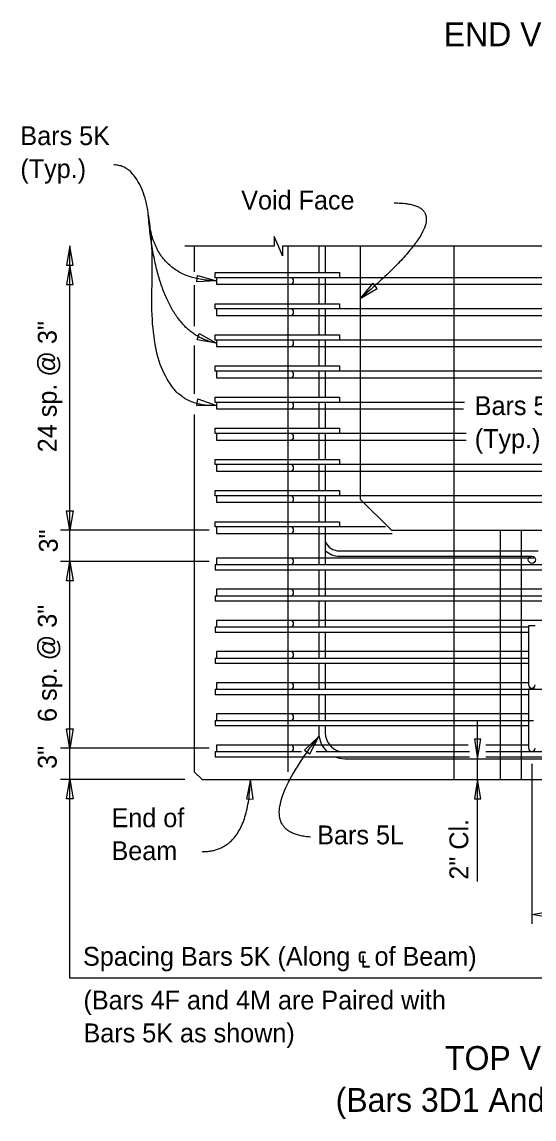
# Model space of a CAD drawing. Extents: x 120658.6 to 120712.1, y 120647.1 to 120669.9.
# Drawn here: x 120659.29 to 120663.4, y 120649.38 to 120658.18 of the extents above; entities that cross this region are included whole.
import ezdxf

# ---------------------------------------------------------------- set-up
doc = ezdxf.new("R2010")
doc.units = 0
for name, color, linetype in [('BeamConc', 7, 'Continuous'), ('BeamConc_h', 7, 'Continuous'), ('Dimension', 7, 'Continuous'), ('Miscellaneous', 7, 'Continuous'), ('Rebar', 7, 'Continuous'), ('Rebar_h', 7, 'Continuous'), ('TextStructures', 7, 'Continuous')]:
    doc.layers.add(name, color=color, linetype=linetype)

msp = doc.modelspace()

# ---------------------------------------------------------------- linework, layer by layer
at = {"layer": 'BeamConc'}
for p, q in [((120660.675, 120656.3833), (120660.675, 120656.1777)), ((120662.0083, 120656.3833), (120662.0083, 120654.3531)), ((120660.675, 120656.0699), (120660.675, 120655.7418)), ((120660.675, 120655.5846), (120660.675, 120655.1981)), ((120660.675, 120655.0319), (120660.675, 120652.1656)), ((120662.0083, 120654.3531), (120662.2583, 120654.1031)), ((120662.2583, 120654.1031), (120666.4578, 120654.1031)), ((120660.675, 120652.1656), (120660.7375, 120652.1031)), ((120660.7375, 120652.1031), (120668.4636, 120652.1031))]:
    msp.add_line(p, q, dxfattribs=at)
at = {"layer": 'BeamConc_h'}
for p, q in [((120661.425, 120656.3833), (120661.425, 120652.1656)), ((120662.7583, 120656.3833), (120662.7583, 120652.1031))]:
    msp.add_line(p, q, dxfattribs=at)
at = {"layer": 'Dimension'}
for p, q in [((120659.6749, 120650.5097), (120659.6749, 120656.3864)), ((120660.7937, 120654.1031), (120659.5993, 120654.1031)), ((120660.7937, 120653.8531), (120659.5993, 120653.8531)), ((120662.9508, 120651.2852), (120662.9508, 120652.5723)), ((120660.7937, 120652.3531), (120659.5993, 120652.3531)), ((120662.4652, 120652.2698), (120662.4652, 120652.2698)), ((120663.3862, 120652.2276), (120663.3862, 120650.9437)), ((120660.5993, 120652.1031), (120659.5993, 120652.1031)), ((120662.4652, 120652.1031), (120662.4652, 120652.1031)), ((120664.0762, 120650.5097), (120659.6749, 120650.5097))]:
    msp.add_line(p, q, dxfattribs=at)
for points in [[(120662.0839, 120656.3833), (120661.3846, 120656.3833), (120661.3846, 120656.3058), (120661.3509, 120656.3833), (120661.3171, 120656.4608), (120661.3171, 120656.3833), (120660.5994, 120656.3833)], [(120668.0994, 120656.3833), (120665.1358, 120656.3833), (120665.1358, 120656.3058), (120665.102, 120656.3833), (120665.0683, 120656.4608), (120665.0683, 120656.3833), (120662.0839, 120656.3833)]]:
    msp.add_lwpolyline(points, dxfattribs=at)
for points in [[(120659.6749, 120656.3864), (120659.6484, 120656.2302), (120659.7014, 120656.2302)], [(120659.6749, 120656.2302), (120659.6484, 120656.0741), (120659.7014, 120656.0741)], [(120660.8531, 120656.1041), (120660.6949, 120656.0954), (120660.7009, 120656.148)], [(120662.0083, 120655.9628), (120662.1444, 120656.0439), (120662.1101, 120656.0842)], [(120660.8531, 120655.604), (120660.6972, 120655.6318), (120660.715, 120655.6817)], [(120660.8531, 120655.104), (120660.6947, 120655.1046), (120660.7037, 120655.1567)], [(120659.6749, 120654.1031), (120659.6485, 120654.2593), (120659.7014, 120654.2593)], [(120659.6749, 120653.8529), (120659.7016, 120653.6972), (120659.6483, 120653.6972)], [(120659.6749, 120652.3529), (120659.6482, 120652.5085), (120659.7016, 120652.5085)], [(120661.675, 120652.4493), (120661.561, 120652.3393), (120661.6036, 120652.3079)], [(120662.9507, 120652.2697), (120662.9774, 120652.4254), (120662.9241, 120652.4254)], [(120659.6749, 120652.1031), (120659.7014, 120651.9469), (120659.6485, 120651.9469)], [(120661.1256, 120652.1031), (120661.0943, 120651.9478), (120661.1472, 120651.9462)], [(120662.9507, 120652.1031), (120662.9241, 120651.9474), (120662.9774, 120651.9474)], [(120663.3862, 120651.0193), (120663.5419, 120651.0459), (120663.5419, 120650.9926)]]:
    msp.add_lwpolyline(points, close=True, dxfattribs=at)
for points in [[(120660.8529, 120655.1038), (120660.3053, 120655.0737), (120660.3647, 120657.0255), (120660.0298, 120657.035)], [(120662.2805, 120656.7296), (120662.9086, 120656.7296), (120662.0083, 120655.9628)], [(120660.8529, 120655.6038), (120660.3843, 120655.6901), (120660.3053, 120656.6311)], [(120660.8529, 120656.1038), (120660.3497, 120656.1141), (120660.3053, 120656.6311)], [(120661.6081, 120651.641), (120661.0763, 120651.677), (120661.675, 120652.4493)], [(120660.7386, 120651.5238), (120661.1076, 120651.5238), (120661.1256, 120652.1031)]]:
    msp.add_open_spline(points, degree=2, dxfattribs=at)
at = {"layer": 'Miscellaneous'}
for p, q in [((120663.1328, 120654.1031), (120663.1328, 120652.1031)), ((120663.2995, 120654.1031), (120663.2995, 120652.1031))]:
    msp.add_line(p, q, dxfattribs=at)
at = {"layer": 'Rebar'}
for p, q in [((120661.675, 120656.3833), (120661.675, 120656.1709)), ((120661.7271, 120656.3833), (120661.7271, 120656.1709)), ((120660.8416, 120656.1709), (120661.8417, 120656.1709)), ((120660.8416, 120656.1292), (120660.8416, 120656.1709)), ((120661.8417, 120656.1292), (120660.8416, 120656.1292)), ((120661.447, 120656.1292), (120660.8531, 120656.1292)), ((120660.8531, 120656.1292), (120660.8531, 120656.0771)), ((120661.675, 120656.1292), (120661.675, 120655.9209)), ((120661.7271, 120656.1292), (120661.7271, 120655.9209)), ((120661.8417, 120656.1709), (120661.8417, 120656.1292)), ((120660.8531, 120656.0771), (120661.447, 120656.0771)), ((120660.8416, 120655.9209), (120661.8417, 120655.9209)), ((120660.8416, 120655.8792), (120660.8416, 120655.9209)), ((120661.8417, 120655.9209), (120661.8417, 120655.8792)), ((120661.8417, 120655.8792), (120660.8416, 120655.8792)), ((120661.447, 120655.8792), (120660.8531, 120655.8792)), ((120660.8531, 120655.8792), (120660.8531, 120655.8271)), ((120661.675, 120655.8792), (120661.675, 120655.6709)), ((120661.7271, 120655.8792), (120661.7271, 120655.6709)), ((120660.8531, 120655.8271), (120661.447, 120655.8271)), ((120660.8416, 120655.6709), (120661.8417, 120655.6709)), ((120660.8416, 120655.6292), (120660.8416, 120655.6709)), ((120661.8417, 120655.6709), (120661.8417, 120655.6292)), ((120661.8417, 120655.6292), (120660.8416, 120655.6292)), ((120661.447, 120655.6292), (120660.8531, 120655.6292)), ((120660.8531, 120655.6292), (120660.8531, 120655.5771)), ((120660.8531, 120655.5771), (120661.447, 120655.5771)), ((120661.675, 120655.6292), (120661.675, 120655.4209)), ((120661.7271, 120655.6292), (120661.7271, 120655.4209)), ((120660.8416, 120655.4209), (120661.8417, 120655.4209)), ((120660.8416, 120655.3792), (120660.8416, 120655.4209)), ((120661.8417, 120655.4209), (120661.8417, 120655.3792)), ((120661.8417, 120655.3792), (120660.8416, 120655.3792)), ((120661.447, 120655.3792), (120660.8531, 120655.3792)), ((120660.8531, 120655.3792), (120660.8531, 120655.3271)), ((120660.8531, 120655.3271), (120661.447, 120655.3271)), ((120661.675, 120655.3792), (120661.675, 120655.1709)), ((120661.7271, 120655.3792), (120661.7271, 120655.1709)), ((120660.8416, 120655.1709), (120661.8417, 120655.1709)), ((120660.8416, 120655.1292), (120660.8416, 120655.1709)), ((120661.8417, 120655.1292), (120660.8416, 120655.1292)), ((120661.447, 120655.1292), (120660.8531, 120655.1292)), ((120660.8531, 120655.1292), (120660.8531, 120655.0771)), ((120661.675, 120655.1292), (120661.675, 120654.9209)), ((120661.7271, 120655.1292), (120661.7271, 120654.9209)), ((120661.8417, 120655.1709), (120661.8417, 120655.1292)), ((120660.8531, 120655.0771), (120661.447, 120655.0771)), ((120660.8416, 120654.9209), (120661.8417, 120654.9209)), ((120660.8416, 120654.8792), (120660.8416, 120654.9209)), ((120661.8417, 120654.8792), (120660.8416, 120654.8792)), ((120661.447, 120654.8792), (120660.8531, 120654.8792)), ((120660.8531, 120654.8792), (120660.8531, 120654.8271)), ((120661.675, 120654.8792), (120661.675, 120654.6709)), ((120661.7271, 120654.8792), (120661.7271, 120654.6709)), ((120661.8417, 120654.9209), (120661.8417, 120654.8792)), ((120660.8531, 120654.8271), (120661.447, 120654.8271)), ((120660.8416, 120654.6709), (120661.8417, 120654.6709)), ((120660.8416, 120654.6292), (120660.8416, 120654.6709)), ((120661.8417, 120654.6292), (120660.8416, 120654.6292)), ((120661.447, 120654.6292), (120660.8531, 120654.6292)), ((120660.8531, 120654.6292), (120660.8531, 120654.5771)), ((120661.675, 120654.6292), (120661.675, 120654.4209)), ((120661.7271, 120654.6292), (120661.7271, 120654.4209)), ((120661.8417, 120654.6709), (120661.8417, 120654.6292)), ((120660.8531, 120654.5771), (120661.447, 120654.5771)), ((120660.8416, 120654.4209), (120661.8417, 120654.4209)), ((120660.8416, 120654.3792), (120660.8416, 120654.4209)), ((120661.8417, 120654.3792), (120660.8416, 120654.3792)), ((120661.447, 120654.3792), (120660.8531, 120654.3792)), ((120660.8531, 120654.3792), (120660.8531, 120654.3271)), ((120661.675, 120654.3792), (120661.675, 120654.1709)), ((120661.7271, 120654.3792), (120661.7271, 120654.1709)), ((120661.8417, 120654.4209), (120661.8417, 120654.3792)), ((120660.8531, 120654.3271), (120661.447, 120654.3271)), ((120660.8416, 120654.1709), (120661.8417, 120654.1709)), ((120660.8416, 120654.1292), (120660.8416, 120654.1709)), ((120661.8417, 120654.1709), (120661.8417, 120654.1292)), ((120661.8417, 120654.1292), (120660.8416, 120654.1292)), ((120661.447, 120654.1292), (120660.8531, 120654.1292)), ((120660.8531, 120654.1292), (120660.8531, 120654.0771)), ((120660.8531, 120654.0771), (120661.447, 120654.0771)), ((120661.675, 120654.1292), (120661.675, 120653.8271)), ((120661.7271, 120654.1292), (120661.7271, 120653.8271)), ((120661.8414, 120653.8948), (120663.386, 120653.8948)), ((120661.8417, 120653.9365), (120663.4354, 120653.9365)), ((120660.8417, 120653.8271), (120660.8417, 120653.7854)), ((120660.8417, 120653.8271), (120667.1494, 120653.8271)), ((120661.447, 120653.8792), (120660.8531, 120653.8792)), ((120660.8531, 120653.8792), (120660.8531, 120653.8271)), ((120660.8531, 120653.8271), (120661.447, 120653.8271)), ((120660.8417, 120653.7854), (120667.1494, 120653.7854)), ((120661.675, 120653.7854), (120661.675, 120653.5771)), ((120661.7271, 120653.7854), (120661.7271, 120653.5771)), ((120660.8417, 120653.5771), (120660.8417, 120653.5354)), ((120660.8417, 120653.5771), (120669.3417, 120653.5771)), ((120661.447, 120653.6292), (120660.8531, 120653.6292)), ((120660.8531, 120653.6292), (120660.8531, 120653.5771)), ((120660.8531, 120653.5771), (120661.447, 120653.5771)), ((120660.8417, 120653.5354), (120669.3417, 120653.5354)), ((120661.675, 120653.5354), (120661.675, 120653.3271)), ((120661.7271, 120653.5354), (120661.7271, 120653.3271)), ((120661.447, 120653.3792), (120660.8531, 120653.3792)), ((120660.8531, 120653.3792), (120660.8531, 120653.3271)), ((120660.8417, 120653.3271), (120660.8417, 120653.2854)), ((120660.8417, 120653.3271), (120663.3602, 120653.3271)), ((120660.8417, 120653.2854), (120663.3602, 120653.2854)), ((120660.8531, 120653.3271), (120661.447, 120653.3271)), ((120661.675, 120653.2854), (120661.675, 120653.0771)), ((120661.7271, 120653.2854), (120661.7271, 120653.0771)), ((120663.3602, 120653.3371), (120663.3602, 120652.8631)), ((120663.4122, 120653.3371), (120663.3602, 120653.3371)), ((120661.447, 120653.1292), (120660.8531, 120653.1292)), ((120660.8531, 120653.1292), (120660.8531, 120653.0771)), ((120660.8417, 120653.0771), (120660.8417, 120653.0354)), ((120660.8417, 120653.0771), (120663.3602, 120653.0771)), ((120660.8417, 120653.0354), (120663.3602, 120653.0354)), ((120660.8531, 120653.0771), (120661.447, 120653.0771)), ((120661.675, 120653.0354), (120661.675, 120652.8271)), ((120661.7271, 120653.0354), (120661.7271, 120652.8271)), ((120661.447, 120652.8792), (120660.8531, 120652.8792)), ((120660.8531, 120652.8792), (120660.8531, 120652.8271)), ((120660.8417, 120652.8271), (120660.8417, 120652.7854)), ((120660.8417, 120652.8271), (120669.3417, 120652.8271)), ((120660.8417, 120652.7854), (120663.3602, 120652.7854)), ((120660.8531, 120652.8271), (120661.447, 120652.8271)), ((120661.675, 120652.7854), (120661.675, 120652.5771)), ((120661.7271, 120652.7854), (120661.7271, 120652.5771)), ((120663.3602, 120652.8271), (120663.3602, 120652.3532)), ((120663.4122, 120652.8271), (120663.3602, 120652.8271)), ((120660.8417, 120652.5771), (120660.8417, 120652.5354)), ((120660.8417, 120652.5771), (120663.0656, 120652.5771)), ((120661.447, 120652.6292), (120660.8531, 120652.6292)), ((120660.8531, 120652.6292), (120660.8531, 120652.5771)), ((120660.8531, 120652.5771), (120661.447, 120652.5771)), ((120663.0656, 120652.5771), (120663.3602, 120652.5771)), ((120660.8417, 120652.5354), (120663.3602, 120652.5354)), ((120661.675, 120652.5354), (120661.675, 120652.4781)), ((120661.7271, 120652.5354), (120661.7271, 120652.4781)), ((120660.8417, 120652.3271), (120660.8417, 120652.2854)), ((120660.8417, 120652.3271), (120661.5294, 120652.3271)), ((120661.447, 120652.3792), (120660.8531, 120652.3792)), ((120660.8531, 120652.3792), (120660.8531, 120652.3271)), ((120660.8531, 120652.3271), (120661.447, 120652.3271)), ((120661.6779, 120652.3271), (120662.8856, 120652.3271)), ((120663.0158, 120652.3271), (120669.3417, 120652.3271)), ((120660.8417, 120652.2854), (120662.8856, 120652.2854)), ((120661.8833, 120652.2698), (120668.3, 120652.2698)), ((120663.0158, 120652.2854), (120669.3417, 120652.2854))]:
    msp.add_line(p, q, dxfattribs=at)
msp.add_circle((120663.3862, 120653.8661), 0.0287, dxfattribs=at)
for centre, radius, start, end in [((120661.447, 120656.1032), 0.026, 270, 90), ((120661.447, 120655.8532), 0.026, 270, 90), ((120661.447, 120655.6032), 0.026, 270, 90), ((120661.447, 120655.3532), 0.026, 270, 90), ((120661.447, 120655.1032), 0.026, 270, 90), ((120661.447, 120654.8532), 0.026, 270, 90), ((120661.447, 120654.6032), 0.026, 270, 90), ((120661.447, 120654.3532), 0.026, 270, 90), ((120661.447, 120654.1032), 0.026, 270, 90), ((120661.8417, 120654.0615), 0.125, 203.55648, 270), ((120661.8417, 120654.0615), 0.1667, 226.58329, 270), ((120661.447, 120653.8532), 0.026, 270, 90), ((120661.447, 120653.6032), 0.026, 270, 90), ((120661.447, 120653.3532), 0.026, 270, 90), ((120661.447, 120653.1032), 0.026, 270, 90), ((120661.447, 120652.8532), 0.026, 270, 90), ((120663.3862, 120652.8631), 0.026, 179.99982, 359.99949), ((120661.447, 120652.6032), 0.026, 270, 90), ((120661.8833, 120652.4781), 0.2083, 179.99988, 226.46663), ((120661.8833, 120652.4781), 0.1562, 180, 255.19156), ((120661.447, 120652.3532), 0.026, 270, 90), ((120663.3862, 120652.3532), 0.026, 179.99982, 359.99949), ((120661.8833, 120652.4781), 0.2083, 247.67157, 270)]:
    msp.add_arc(centre, radius, start, end, dxfattribs=at)
at = {"layer": 'Rebar_h'}
for p, q in [((120660.8531, 120654.1292), (120660.8531, 120654.0771)), ((120662.2115, 120654.1292), (120660.8531, 120654.1292)), ((120660.8531, 120654.0771), (120662.2635, 120654.0771))]:
    msp.add_line(p, q, dxfattribs=at)
for points in [[(120669.3303, 120656.1292), (120660.8531, 120656.1292), (120660.8531, 120656.0771), (120669.3303, 120656.0771)], [(120669.3303, 120655.6292), (120660.8531, 120655.6292), (120660.8531, 120655.5771), (120669.3303, 120655.5771)]]:
    msp.add_lwpolyline(points, close=True, dxfattribs=at)
for points in [[(120664.8016, 120655.8792), (120660.8531, 120655.8792), (120660.8531, 120655.8271), (120664.8016, 120655.8271)], [(120666.894, 120655.3792), (120660.8531, 120655.3792), (120660.8531, 120655.3271), (120666.9015, 120655.3271)], [(120662.8445, 120655.1292), (120660.8531, 120655.1292), (120660.8531, 120655.0771), (120662.838, 120655.0771)], [(120662.859, 120654.8792), (120660.8531, 120654.8792), (120660.8531, 120654.8271), (120662.859, 120654.8271)], [(120666.8374, 120654.6292), (120660.8531, 120654.6292), (120660.8531, 120654.5771), (120666.8374, 120654.5771)], [(120666.8374, 120654.3792), (120660.8531, 120654.3792), (120660.8531, 120654.3271), (120666.8374, 120654.3271)], [(120663.4011, 120653.8792), (120660.8531, 120653.8792), (120660.8531, 120653.8271), (120663.399, 120653.8271)], [(120668.3586, 120653.6292), (120660.8531, 120653.6292), (120660.8531, 120653.5771), (120663.399, 120653.5771)], [(120668.3586, 120653.3792), (120660.8531, 120653.3792), (120660.8531, 120653.3271), (120663.3602, 120653.3271)], [(120663.3602, 120653.1292), (120660.8531, 120653.1292), (120660.8531, 120653.0771), (120663.3602, 120653.0771)], [(120663.3602, 120652.8792), (120660.8531, 120652.8792), (120660.8531, 120652.8271), (120669.3303, 120652.8271), (120669.3303, 120652.8792), (120666.7456, 120652.8792)], [(120663.3602, 120652.6292), (120660.8531, 120652.6292), (120660.8531, 120652.5771), (120663.399, 120652.5771)], [(120662.8733, 120652.3792), (120660.8531, 120652.3792), (120660.8531, 120652.3271), (120661.5372, 120652.3271)], [(120661.6543, 120652.3271), (120662.8856, 120652.3271)], [(120663.3602, 120652.3792), (120663.0158, 120652.3792)], [(120663.0158, 120652.3271), (120669.3303, 120652.3271), (120669.3303, 120652.3792), (120667.1177, 120652.3792)]]:
    msp.add_lwpolyline(points, dxfattribs=at)

# ---------------------------------------------------------------- texts
at = {"layer": 'Dimension'}
for s, height, p in [('Bars 5K', 0.1512, (120659.278, 120657.1932)), ('(Typ.)', 0.1512, (120659.278, 120656.9292)), ('End of', 0.1512, (120660.0099, 120651.7201)), ('Beam', 0.1512, (120660.0099, 120651.4561)), ('(Bars 4F and 4M are Paired with', 0.1512, (120659.785, 120650.258)), ('Bars 5K as shown)', 0.1512, (120659.785, 120649.994)), ('TOP VIEW OF END DIAPHRAGM', 0.192, (120662.6888, 120649.7723)), ('(Bars 3D1 And 3D2 Not Shown For Clarity)', 0.192, (120661.8102, 120649.4363))]:
    msp.add_text(s, height=height, dxfattribs=at).set_placement(p)
at = {"layer": 'TextStructures'}
for s, height, p in [('END VIEW AT END DIAPHRAGM', 0.192, (120662.6787, 120657.9867)), ('Void Face', 0.1512, (120661.0518, 120656.6764)), ('Bars 5B', 0.1512, (120662.9271, 120655.0271)), ('(Typ.)', 0.1512, (120662.9271, 120654.7631)), ('Bars 5L', 0.1512, (120661.6622, 120651.5827)), ('Spacing Bars 5K (Along ℄ of Beam)', 0.1512, (120659.7813, 120650.6087))]:
    msp.add_text(s, height=height, dxfattribs=at).set_placement(p)
for s, p in [('24 sp. @ 3"', (120659.5695, 120654.7287)), ('3"', (120659.5782, 120653.925)), ('6 sp. @ 3"', (120659.5695, 120652.5648)), ('3"', (120659.5695, 120652.1885)), ('2" Cl.', (120662.8752, 120651.2996))]:
    msp.add_text(s, height=0.1512, rotation=90, dxfattribs=at).set_placement(p)

doc.saveas('drawing.dxf')
